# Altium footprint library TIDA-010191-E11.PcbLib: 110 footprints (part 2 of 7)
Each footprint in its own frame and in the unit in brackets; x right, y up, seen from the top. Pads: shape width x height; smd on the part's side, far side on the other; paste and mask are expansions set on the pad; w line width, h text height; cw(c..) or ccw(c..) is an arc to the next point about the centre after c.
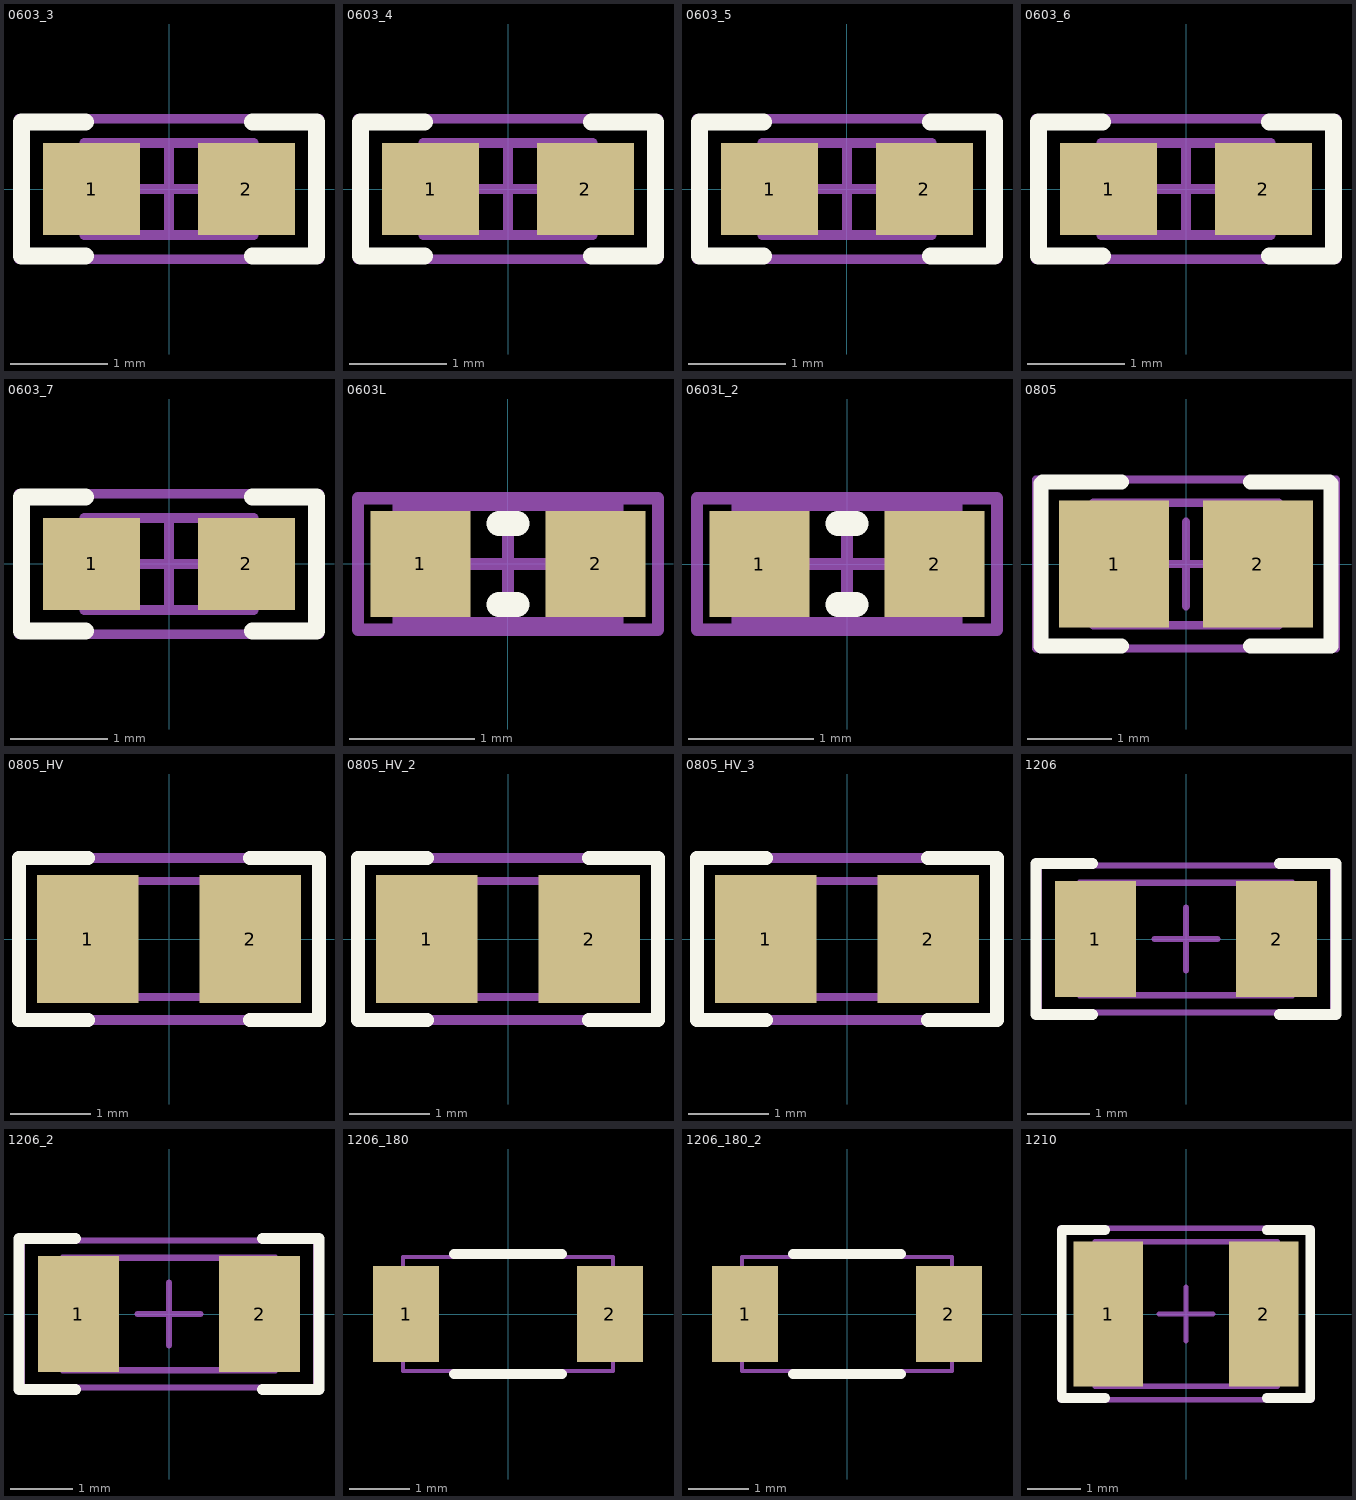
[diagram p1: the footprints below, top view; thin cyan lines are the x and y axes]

## 0603_3 [mm]
pads (2):
  rect 1x0.95 smd: 1(-0.8,0) 2(0.8,0)
Top Overlay:
  lines w0.178: -0.864,-0.691 -1.524,-0.691 -1.524,0.693 -0.864,0.693 ; 0.864,-0.691 1.524,-0.691 1.524,0.693 0.864,0.693
Mechanical 5:
  lines w0.1: -1.55,-0.725 1.55,-0.725 1.55,0.725 -1.55,0.725 -1.55,-0.725
  text ".Designator" at -1.397,-0.381 h0.76
Mechanical 13:
  lines w0.1: -0.55,-0.475 -0.55,0.475 ; 0.55,-0.475 0.55,0.475 ; -0.875,-0.475 -0.875,0.475 0.875,0.475 0.875,-0.475 -0.875,-0.475
Mechanical 15:
  lines w0.1: -0.475,0 0.475,0 ; 0,-0.475 0,0.475 ; -1.55,-0.725 -1.55,0.725 1.55,0.725 1.55,-0.725 -1.55,-0.725
3D body: height 1, standoff 0, extent 0.551,-0.474 0.874,0.474
3D body: height 1, standoff 0, extent -0.549,-0.474 0.549,0.474
3D body: height 1, standoff 0, extent -0.874,-0.474 -0.551,0.474

## 0603_4 [mm]
pads (2):
  rect 1x0.95 smd: 1(-0.8,0) 2(0.8,0)
Top Overlay:
  lines w0.178: -0.864,-0.691 -1.524,-0.691 -1.524,0.693 -0.864,0.693 ; 0.864,-0.691 1.524,-0.691 1.524,0.693 0.864,0.693
Mechanical 5:
  lines w0.1: -1.55,-0.725 1.55,-0.725 1.55,0.725 -1.55,0.725 -1.55,-0.725
  text ".Designator" at -1.397,-0.381 h0.76
Mechanical 13:
  lines w0.1: -0.55,-0.475 -0.55,0.475 ; 0.55,-0.475 0.55,0.475 ; -0.875,-0.475 -0.875,0.475 0.875,0.475 0.875,-0.475 -0.875,-0.475
Mechanical 15:
  lines w0.1: -0.475,0 0.475,0 ; 0,-0.475 0,0.475 ; -1.55,-0.725 -1.55,0.725 1.55,0.725 1.55,-0.725 -1.55,-0.725
3D body: height 1, standoff 0, extent 0.551,-0.474 0.874,0.474
3D body: height 1, standoff 0, extent -0.549,-0.474 0.549,0.474
3D body: height 1, standoff 0, extent -0.874,-0.474 -0.551,0.474

## 0603_5 [mm]
pads (2):
  rect 1x0.95 smd: 1(-0.8,0) 2(0.8,0)
Top Overlay:
  lines w0.178: -0.864,-0.691 -1.524,-0.691 -1.524,0.693 -0.864,0.693 ; 0.864,-0.691 1.524,-0.691 1.524,0.693 0.864,0.693
Mechanical 5:
  lines w0.1: -1.55,-0.725 1.55,-0.725 1.55,0.725 -1.55,0.725 -1.55,-0.725
  text ".Designator" at 0.904,0.243 h0.64
Mechanical 13:
  lines w0.1: -0.55,-0.475 -0.55,0.475 ; 0.55,-0.475 0.55,0.475 ; -0.875,-0.475 -0.875,0.475 0.875,0.475 0.875,-0.475 -0.875,-0.475
Mechanical 15:
  lines w0.1: -0.475,0 0.475,0 ; 0,-0.475 0,0.475 ; -1.55,-0.725 -1.55,0.725 1.55,0.725 1.55,-0.725 -1.55,-0.725
3D body: height 1, standoff 0, extent 0.551,-0.474 0.874,0.474
3D body: height 1, standoff 0, extent -0.549,-0.474 0.549,0.474
3D body: height 1, standoff 0, extent -0.874,-0.474 -0.551,0.474

## 0603_6 [mm]
pads (2):
  rect 1x0.95 smd: 1(-0.8,0) 2(0.8,0)
Top Overlay:
  lines w0.178: -0.864,-0.691 -1.524,-0.691 -1.524,0.693 -0.864,0.693 ; 0.864,-0.691 1.524,-0.691 1.524,0.693 0.864,0.693
Mechanical 5:
  lines w0.1: -1.55,-0.725 1.55,-0.725 1.55,0.725 -1.55,0.725 -1.55,-0.725
  text ".Designator" at 0.589,0.318 h0.64
Mechanical 13:
  lines w0.1: -0.55,-0.475 -0.55,0.475 ; 0.55,-0.475 0.55,0.475 ; -0.875,-0.475 -0.875,0.475 0.875,0.475 0.875,-0.475 -0.875,-0.475
Mechanical 15:
  lines w0.1: -0.475,0 0.475,0 ; 0,-0.475 0,0.475 ; -1.55,-0.725 -1.55,0.725 1.55,0.725 1.55,-0.725 -1.55,-0.725
3D body: height 1, standoff 0, extent 0.551,-0.474 0.874,0.474
3D body: height 1, standoff 0, extent -0.549,-0.474 0.549,0.474
3D body: height 1, standoff 0, extent -0.874,-0.474 -0.551,0.474

## 0603_7 [mm]
pads (2):
  rect 1x0.95 smd: 1(-0.8,0) 2(0.8,0)
Top Overlay:
  lines w0.178: -0.864,-0.691 -1.524,-0.691 -1.524,0.693 -0.864,0.693 ; 0.864,-0.691 1.524,-0.691 1.524,0.693 0.864,0.693
Mechanical 5:
  lines w0.1: -1.55,-0.725 -1.55,0.725 1.55,0.725 1.55,-0.725 -1.55,-0.725
  text ".Designator" at 1.118,0.33 h0.64
Mechanical 13:
  lines w0.1: -0.55,-0.475 -0.55,0.475 ; 0.55,-0.475 0.55,0.475 ; -0.875,-0.475 0.875,-0.475 0.875,0.475 -0.875,0.475 -0.875,-0.475
Mechanical 15:
  lines w0.1: -0.475,0 0.475,0 ; 0,-0.475 0,0.475 ; -1.55,-0.725 1.55,-0.725 1.55,0.725 -1.55,0.725 -1.55,-0.725
3D body: height 1, standoff 0, extent -0.874,-0.474 -0.551,0.474
3D body: height 1, standoff 0, extent -0.549,-0.474 0.549,0.474
3D body: height 1, standoff 0, extent 0.551,-0.474 0.874,0.474

## 0603L [mm] "0603 from SM-752 data"
height 1
pads (2):
  rect 0.8x0.85 smd: 1(-0.7,0) 2(0.7,0)
Top Overlay:
  lines w0.2: -0.071,-0.325 0.071,-0.325 ; -0.071,0.325 0.071,0.325
Mechanical 5:
  lines w0.1: -1.2,-0.525 1.2,-0.525 1.2,0.525 -1.2,0.525 -1.2,-0.525
  text ".Designator" at 0.784,0.303 h0.64
Mechanical 13:
  lines w0.1: -0.55,-0.475 -0.55,0.475 ; 0.55,-0.475 0.55,0.475 ; -0.875,-0.475 0.875,-0.475 0.875,0.475 -0.875,0.475 -0.875,-0.475
Mechanical 15:
  lines w0.1: -0.475,0 0.475,0 ; 0,-0.475 0,0.475 ; -1.2,-0.525 -1.2,0.525 1.2,0.525 1.2,-0.525 -1.2,-0.525
3D body: height 1, standoff 0, extent -0.874,-0.474 -0.551,0.474
3D body: height 1, standoff 0, extent -0.549,-0.474 0.549,0.474
3D body: height 1, standoff 0, extent 0.551,-0.474 0.874,0.474

## 0603L_2 [mm]
pads (2):
  rect 0.8x0.85 smd: 1(-0.7,0) 2(0.7,0)
Top Overlay:
  lines w0.2: -0.071,-0.325 0.071,-0.325 ; -0.071,0.325 0.071,0.325
Mechanical 5:
  lines w0.1: -1.2,-0.525 1.2,-0.525 1.2,0.525 -1.2,0.525 -1.2,-0.525
  text ".Designator" at -0.795,-0.312 h0.64
Mechanical 13:
  lines w0.1: -0.55,-0.475 -0.55,0.475 ; 0.55,-0.475 0.55,0.475 ; -0.875,-0.475 0.875,-0.475 0.875,0.475 -0.875,0.475 -0.875,-0.475
Mechanical 15:
  lines w0.1: -0.475,0 0.475,0 ; 0,-0.475 0,0.475 ; -1.2,-0.525 -1.2,0.525 1.2,0.525 1.2,-0.525 -1.2,-0.525
3D body: height 1, standoff 0, extent -0.874,-0.474 -0.551,0.474
3D body: height 1, standoff 0, extent -0.549,-0.474 0.549,0.474
3D body: height 1, standoff 0, extent 0.551,-0.474 0.874,0.474

## 0805 [mm] "0805 from SM-752 data"
height 1.45
pads (2):
  rect 1.3x1.5 smd: 1(-0.85,0) 2(0.85,0)
Top Overlay:
  lines w0.178: -0.762,-0.968 -1.717,-0.968 -1.717,0.95 -1.699,0.968 -0.762,0.968 ; 0.762,-0.968 1.717,-0.968 1.717,0.95 1.699,0.968 0.762,0.968
Mechanical 5:
  lines w0.1: -1.775,-1 -1.775,1 1.775,1 1.775,-1 -1.775,-1
  text ".Designator" at -1.525,-0.425 h0.81
Mechanical 13:
  lines w0.1: -0.65,-0.725 -0.65,0.725 ; 0.65,-0.725 0.65,0.725 ; -1.1,-0.725 -1.1,0.725 1.1,0.725 1.1,-0.725 -1.1,-0.725
Mechanical 15:
  lines w0.1: -0.5,0 0.5,0 ; 0,-0.5 0,0.5 ; -1.775,-1 -1.775,1 1.775,1 1.775,-1 -1.775,-1
3D body: height 1.45, standoff 0, extent 0.651,-0.724 1.099,0.724
3D body: height 1.45, standoff 0, extent -0.649,-0.724 0.649,0.724
3D body: height 1.45, standoff 0, extent -1.099,-0.724 -0.651,0.724

## 0805_HV [mil] "0805 with 30mil clearance between pads"
height 57.09
pads (2):
  rect 50x63 smd: 1(-40,0) 2(40,0)
Top Overlay:
  lines w7: -40,-40 -74,-40 -74,0 -74,40 -40,40 ; 40,-40 74,-40 74,0 74,40 40,40
Mechanical 5:
  lines w5: -74,-40 -74,40 74,40 74,-40 -74,-40
  text ".Designator" at -64,-17 h35
Mechanical 13:
  lines w3.94: -25.59,-28.54 -25.59,28.54 ; 25.59,-28.54 25.59,28.54 ; -43.31,-28.54 -43.31,28.54 43.31,28.54 43.31,-28.54 -43.31,-28.54
3D body: height 57.09, standoff 0, extent 25.61,-28.52 43.29,28.52
3D body: height 57.09, standoff 0, extent -25.57,-28.52 25.57,28.52
3D body: height 57.09, standoff 0, extent -43.29,-28.52 -25.61,28.52

## 0805_HV_2 [mil]
pads (2):
  rect 50x63 smd: 1(-40,0) 2(40,0)
Top Overlay:
  lines w7: -40,-40 -74,-40 -74,0 -74,40 -40,40 ; 40,-40 74,-40 74,0 74,40 40,40
Mechanical 5:
  lines w5: -74,-40 74,-40 74,40 -74,40 -74,-40
  text ".Designator" at -64,-17 h35
Mechanical 13:
  lines w3.94: -25.59,-28.54 -25.59,28.54 ; 25.59,-28.54 25.59,28.54 ; -43.31,-28.54 43.31,-28.54 43.31,28.54 -43.31,28.54 -43.31,-28.54
3D body: height 57.09, standoff 0, extent -43.29,-28.52 -25.61,28.52
3D body: height 57.09, standoff 0, extent -25.57,-28.52 25.57,28.52
3D body: height 57.09, standoff 0, extent 25.61,-28.52 43.29,28.52

## 0805_HV_3 [mil]
pads (2):
  rect 50x63 smd: 1(-40,0) 2(40,0)
Top Overlay:
  lines w7: -40,-40 -74,-40 -74,0 -74,40 -40,40 ; 40,-40 74,-40 74,0 74,40 40,40
Mechanical 5:
  lines w5: -74,-40 74,-40 74,40 -74,40 -74,-40
  text ".Designator" at -64,-17 h35
Mechanical 13:
  lines w3.94: -25.59,-28.54 -25.59,28.54 ; 25.59,-28.54 25.59,28.54 ; -43.31,-28.54 43.31,-28.54 43.31,28.54 -43.31,28.54 -43.31,-28.54
3D body: height 57.09, standoff 0, extent -43.29,-28.52 -25.61,28.52
3D body: height 57.09, standoff 0, extent -25.57,-28.52 25.57,28.52
3D body: height 57.09, standoff 0, extent 25.61,-28.52 43.29,28.52

## 1206 [mm] "1206 from SM-752 data"
height 1.35
pads (2):
  rect 1.3x1.85 smd: 1(-1.45,0) 2(1.45,0)
Top Overlay:
  lines w0.178: -1.5,-1.21 -2.4,-1.21 -2.4,1.21 -1.5,1.21 ; 1.5,-1.21 2.4,-1.21 2.4,1.21 1.5,1.21
Mechanical 5:
  lines w0.1: -1.7,-0.9 -1.7,0.9 1.7,0.9 1.7,-0.9 -1.7,-0.9
  text ".Designator" at -1.475,-0.4 h0.81
Mechanical 13:
  lines w0.1: -1.2,-0.9 -1.2,0.9 ; 1.2,-0.9 1.2,0.9 ; -1.7,-0.9 -1.7,0.9 1.7,0.9 1.7,-0.9 -1.7,-0.9
Mechanical 15:
  lines w0.1: -0.5,0 0.5,0 ; 0,-0.5 0,0.5 ; -2.35,-1.175 -2.35,1.175 2.35,1.175 2.35,-1.175 -2.35,-1.175
3D body: height 1.35, standoff 0, extent 1.201,-0.899 1.699,0.899
3D body: height 1.35, standoff 0, extent -1.199,-0.899 1.199,0.899
3D body: height 1.35, standoff 0, extent -1.699,-0.899 -1.201,0.899

## 1206_2 [mm]
pads (2):
  rect 1.3x1.85 smd: 1(-1.45,0) 2(1.45,0)
Top Overlay:
  lines w0.178: -1.5,-1.21 -2.4,-1.21 -2.4,1.21 -1.5,1.21 ; 1.5,-1.21 2.4,-1.21 2.4,1.21 1.5,1.21
Mechanical 5:
  lines w0.1: -1.7,-0.9 1.7,-0.9 1.7,0.9 -1.7,0.9 -1.7,-0.9
  text ".Designator" at -1.475,-0.4 h0.81
Mechanical 13:
  lines w0.1: -1.2,-0.9 -1.2,0.9 ; 1.2,-0.9 1.2,0.9 ; -1.7,-0.9 1.7,-0.9 1.7,0.9 -1.7,0.9 -1.7,-0.9
Mechanical 15:
  lines w0.1: -0.5,0 0.5,0 ; 0,-0.5 0,0.5 ; -2.35,-1.175 2.35,-1.175 2.35,1.175 -2.35,1.175 -2.35,-1.175
3D body: height 1.35, standoff 0, extent -1.699,-0.899 -1.201,0.899
3D body: height 1.35, standoff 0, extent -1.199,-0.899 1.199,0.899
3D body: height 1.35, standoff 0, extent 1.201,-0.899 1.699,0.899

## 1206_180 [mm] "1206_180"
height 1.8
pads (2):
  rect 1.1x1.6 smd: 1(-1.7,0) 2(1.7,0)
Top Overlay:
  lines w0.17: -0.9,-1 0.9,-1 ; -0.9,1 0.9,1
Mechanical 5:
  lines w0.07: -1.75,-0.95 1.75,-0.95 1.75,0.95 -1.75,0.95 -1.75,-0.95
  text ".Designator" at -1.5,-0.4 h0.81
3D body: height 1.8, standoff 0, extent -1.749,-0.949 -1.301,0.949
3D body: height 1.8, standoff 0, extent -1.299,-0.949 1.299,0.949
3D body: height 1.8, standoff 0, extent 1.301,-0.949 1.749,0.949

## 1206_180_2 [mm]
pads (2):
  rect 1.1x1.6 smd: 1(-1.7,0) 2(1.7,0)
Top Overlay:
  lines w0.17: -0.9,-1 0.9,-1 ; -0.9,1 0.9,1
Mechanical 5:
  lines w0.07: -1.75,-0.95 -1.75,0.95 1.75,0.95 1.75,-0.95 -1.75,-0.95
  text ".Designator" at -1.5,-0.4 h0.81
3D body: height 1.8, standoff 0, extent 1.301,-0.949 1.749,0.949
3D body: height 1.8, standoff 0, extent -1.299,-0.949 1.299,0.949
3D body: height 1.8, standoff 0, extent -1.749,-0.949 -1.301,0.949

## 1210 [mm] "1210 from SM-752 data"
height 1.35
pads (2):
  rect 1.3x2.7 smd: 1(-1.45,0) 2(1.45,0)
Top Overlay:
  lines w0.178: -1.511,-1.568 -2.316,-1.568 -2.316,1.568 -1.511,1.568 ; 1.511,-1.568 2.316,-1.568 2.316,1.568 1.511,1.568
Mechanical 5:
  lines w0.1: -1.7,-1.35 1.7,-1.35 1.7,1.35 -1.7,1.35 -1.7,-1.35
  text ".Designator" at -1.4,-0.375 h0.76
Mechanical 13:
  lines w0.1: -1.2,-1.35 -1.2,1.35 ; 1.2,-1.35 1.2,1.35 ; -1.7,-1.35 -1.7,1.35 1.7,1.35 1.7,-1.35 -1.7,-1.35
Mechanical 15:
  lines w0.1: -0.5,0 0.5,0 ; 0,-0.5 0,0.5 ; -2.35,-1.6 -2.35,1.6 2.35,1.6 2.35,-1.6 -2.35,-1.6
3D body: height 1.35, standoff 0, extent -1.699,-1.349 -1.201,1.349
3D body: height 1.35, standoff 0, extent -1.199,-1.349 1.199,1.349
3D body: height 1.35, standoff 0, extent 1.201,-1.349 1.699,1.349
